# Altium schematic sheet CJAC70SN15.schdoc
size 127 x 101 mm
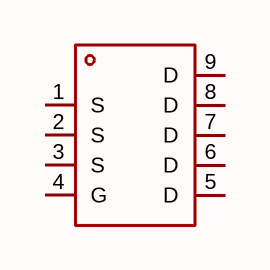
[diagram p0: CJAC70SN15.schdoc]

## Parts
Q?  cjac70sn15  [DFN-8_L5.8-W4.9-P1.27-LS6.1-BL-2]  (value not drawn)

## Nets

Not connected (* = marked no-connect by the designer): Q? 1(S) 2(S) 3(S) 4(G) 5(D) 6(D) 7(D) 8(D) 9(D)

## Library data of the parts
Q? = cjac70sn15: 数量:1个N沟道;漏源电压(Vdss):150V;连续漏极电流(Id):70A;导通电阻(RDS(on)):10mΩ@10V;耗散功率(Pd):114W;阈值电压(Vgs(th)):2V;; Manufacturer: CJ(江苏长电/长晶); AddInBom: yes; ModelId: d917b484949b4e6a87c82dc8ef0b7e62; ModelTransform: 202.7555,240.157,0,0,0,0,0,0,0; Number: 1个N沟道; Drain to Source Voltage: 150V; Current - Continuous Drain(Id): 70A; Pd - Power Dissipation: 114W; Gate Threshold Voltage (Vgs(th)): 2V; Gate Charge(Qg): 45nC; Input Capacitance(Ciss): 5.8nF; Reverse Transfer Capacitance (Crss@Vds): 13.5pF; Type: N沟道; Output Capacitance(Coss): 252pF; Vgs: ±20V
